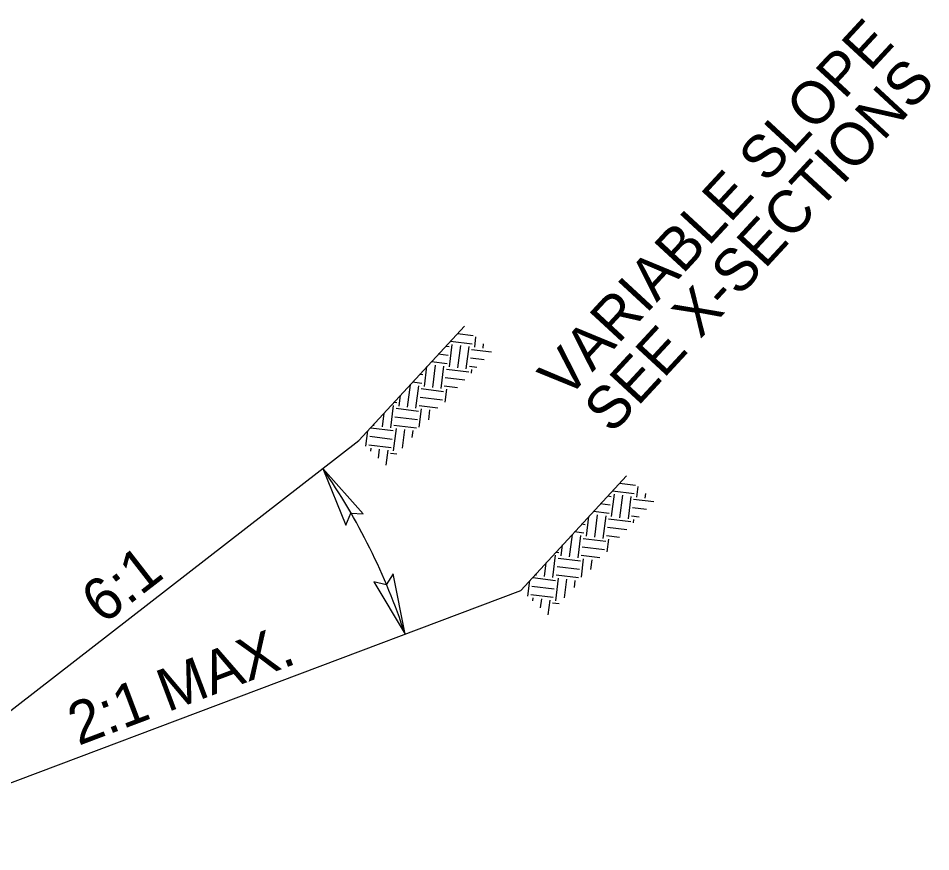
# Model space of a CAD drawing. Extents: x 1768274 to 1769121, y 999922 to 1000687.
# Drawn here: x 1769052.44 to 1769082.83, y 1000010.14 to 1000037.91 of the extents above; entities that cross this region are included whole.
import ezdxf

# ---------------------------------------------------------------- set-up
doc = ezdxf.new("R2010")
doc.units = 0
doc.layers.add('E_NCDOT_Terrain_Model_Triangles', color=7, linetype='Continuous')

msp = doc.modelspace()

# ---------------------------------------------------------------- linework, layer by layer
at = {"layer": 'E_NCDOT_Terrain_Model_Triangles'}
for p, q in [((1769063.78, 1000023.837), (1769067.304, 1000027.65)), ((1769063.78, 1000023.837), (1769067.304, 1000027.65)), ((1769067.56, 1000027.051), (1769066.834, 1000027.141)), ((1769067.56, 1000027.051), (1769066.834, 1000027.141)), ((1769067.595, 1000027.331), (1769067.07, 1000027.396)), ((1769067.595, 1000027.331), (1769067.07, 1000027.396)), ((1769067.642, 1000026.947), (1769067.685, 1000027.298)), ((1769067.642, 1000026.947), (1769067.685, 1000027.298)), ((1769066.791, 1000026.957), (1769066.677, 1000026.971)), ((1769066.791, 1000026.957), (1769066.677, 1000026.971)), ((1769066.803, 1000026.293), (1769066.896, 1000027.039)), ((1769066.803, 1000026.293), (1769066.896, 1000027.039)), ((1769067.083, 1000026.258), (1769067.175, 1000027.004)), ((1769067.083, 1000026.258), (1769067.175, 1000027.004)), ((1769067.363, 1000026.224), (1769067.455, 1000026.97)), ((1769067.363, 1000026.224), (1769067.455, 1000026.97)), ((1769068.205, 1000026.782), (1769067.537, 1000026.865)), ((1769068.205, 1000026.782), (1769067.537, 1000026.865)), ((1769067.922, 1000026.912), (1769067.94, 1000027.062)), ((1769067.922, 1000026.912), (1769067.94, 1000027.062)), ((1769066.756, 1000026.677), (1769066.428, 1000026.718)), ((1769066.756, 1000026.677), (1769066.428, 1000026.718)), ((1769067.961, 1000026.528), (1769067.502, 1000026.585)), ((1769067.961, 1000026.528), (1769067.502, 1000026.585)), ((1769065.965, 1000025.639), (1769066.047, 1000026.303)), ((1769065.965, 1000025.639), (1769066.047, 1000026.303)), ((1769066.722, 1000026.398), (1769066.206, 1000026.461)), ((1769066.722, 1000026.398), (1769066.206, 1000026.461)), ((1769066.245, 1000025.604), (1769066.337, 1000026.35)), ((1769066.245, 1000025.604), (1769066.337, 1000026.35)), ((1769066.525, 1000025.57), (1769066.617, 1000026.316)), ((1769066.525, 1000025.57), (1769066.617, 1000026.316)), ((1769067.716, 1000026.275), (1769067.468, 1000026.305)), ((1769067.716, 1000026.275), (1769067.468, 1000026.305)), ((1769065.918, 1000026.023), (1769065.803, 1000026.038)), ((1769065.918, 1000026.023), (1769065.803, 1000026.038)), ((1769067.309, 1000025.851), (1769066.664, 1000025.931)), ((1769067.309, 1000025.851), (1769066.664, 1000025.931)), ((1769067.445, 1000026.119), (1769066.699, 1000026.211)), ((1769067.445, 1000026.119), (1769066.699, 1000026.211)), ((1769067.535, 1000026.087), (1769067.55, 1000026.201)), ((1769067.535, 1000026.087), (1769067.55, 1000026.201)), ((1769065.406, 1000024.95), (1769065.499, 1000025.697)), ((1769065.406, 1000024.95), (1769065.499, 1000025.697)), ((1769065.883, 1000025.744), (1769065.569, 1000025.783)), ((1769065.883, 1000025.744), (1769065.569, 1000025.783)), ((1769065.686, 1000024.916), (1769065.778, 1000025.662)), ((1769065.686, 1000024.916), (1769065.778, 1000025.662)), ((1769067.065, 1000025.598), (1769066.629, 1000025.651)), ((1769067.065, 1000025.598), (1769066.629, 1000025.651)), ((1769065.127, 1000024.985), (1769065.172, 1000025.351)), ((1769065.127, 1000024.985), (1769065.172, 1000025.351)), ((1769066.606, 1000025.465), (1769065.86, 1000025.557)), ((1769066.606, 1000025.465), (1769065.86, 1000025.557)), ((1769066.658, 1000025.121), (1769066.711, 1000025.547)), ((1769066.658, 1000025.121), (1769066.711, 1000025.547)), ((1769064.848, 1000024.262), (1769064.94, 1000025.008)), ((1769064.848, 1000024.262), (1769064.94, 1000025.008)), ((1769065.045, 1000025.09), (1769064.944, 1000025.102)), ((1769065.045, 1000025.09), (1769064.944, 1000025.102)), ((1769066.572, 1000025.185), (1769065.826, 1000025.277)), ((1769066.572, 1000025.185), (1769065.826, 1000025.277)), ((1769064.568, 1000024.296), (1769064.625, 1000024.756)), ((1769064.568, 1000024.296), (1769064.625, 1000024.756)), ((1769065.768, 1000024.811), (1769065.022, 1000024.903)), ((1769065.768, 1000024.811), (1769065.022, 1000024.903)), ((1769066.414, 1000024.921), (1769065.791, 1000024.998)), ((1769066.414, 1000024.921), (1769065.791, 1000024.998)), ((1769065.797, 1000024.28), (1769065.873, 1000024.893)), ((1769065.797, 1000024.28), (1769065.873, 1000024.893)), ((1769066.112, 1000024.529), (1769066.153, 1000024.858)), ((1769066.112, 1000024.529), (1769066.153, 1000024.858)), ((1769064.288, 1000024.331), (1769064.297, 1000024.398)), ((1769064.288, 1000024.331), (1769064.297, 1000024.398)), ((1769065.733, 1000024.531), (1769064.987, 1000024.623)), ((1769065.733, 1000024.531), (1769064.987, 1000024.623)), ((1769064.014, 1000023.647), (1769064.078, 1000024.16)), ((1769064.014, 1000023.647), (1769064.078, 1000024.16)), ((1769064.93, 1000024.157), (1769064.183, 1000024.249)), ((1769064.93, 1000024.157), (1769064.183, 1000024.249)), ((1769064.942, 1000023.493), (1769065.034, 1000024.239)), ((1769064.942, 1000023.493), (1769065.034, 1000024.239)), ((1769065.699, 1000024.251), (1769064.953, 1000024.344)), ((1769065.699, 1000024.251), (1769064.953, 1000024.344)), ((1769065.237, 1000023.583), (1769065.314, 1000024.204)), ((1769065.237, 1000023.583), (1769065.314, 1000024.204)), ((1769065.565, 1000023.938), (1769065.594, 1000024.17)), ((1769065.565, 1000023.938), (1769065.594, 1000024.17)), ((1769046.112, 1000010.138), (1769063.78, 1000023.837)), ((1769064.895, 1000023.877), (1769064.149, 1000023.97)), ((1769064.895, 1000023.877), (1769064.149, 1000023.97)), ((1769064.86, 1000023.597), (1769064.114, 1000023.69)), ((1769064.86, 1000023.597), (1769064.114, 1000023.69)), ((1769064.184, 1000023.49), (1769064.196, 1000023.585)), ((1769064.184, 1000023.49), (1769064.196, 1000023.585)), ((1769064.439, 1000023.254), (1769064.476, 1000023.55)), ((1769064.439, 1000023.254), (1769064.476, 1000023.55)), ((1769064.694, 1000023.019), (1769064.756, 1000023.516)), ((1769064.694, 1000023.019), (1769064.756, 1000023.516)), ((1769065.053, 1000023.384), (1769064.837, 1000023.411)), ((1769065.053, 1000023.384), (1769064.837, 1000023.411)), ((1769069.178, 1000018.847), (1769072.702, 1000022.66)), ((1769069.178, 1000018.847), (1769072.702, 1000022.66)), ((1769072.993, 1000022.342), (1769072.468, 1000022.407)), ((1769072.993, 1000022.342), (1769072.468, 1000022.407)), ((1769073.04, 1000021.957), (1769073.083, 1000022.308)), ((1769073.04, 1000021.957), (1769073.083, 1000022.308)), ((1769072.189, 1000021.968), (1769072.075, 1000021.982)), ((1769072.189, 1000021.968), (1769072.075, 1000021.982)), ((1769072.201, 1000021.303), (1769072.294, 1000022.049)), ((1769072.201, 1000021.303), (1769072.294, 1000022.049)), ((1769072.958, 1000022.062), (1769072.232, 1000022.152)), ((1769072.958, 1000022.062), (1769072.232, 1000022.152)), ((1769072.481, 1000021.269), (1769072.573, 1000022.015)), ((1769072.481, 1000021.269), (1769072.573, 1000022.015)), ((1769072.761, 1000021.234), (1769072.853, 1000021.98)), ((1769072.761, 1000021.234), (1769072.853, 1000021.98)), ((1769073.32, 1000021.922), (1769073.338, 1000022.072)), ((1769073.32, 1000021.922), (1769073.338, 1000022.072)), ((1769072.154, 1000021.688), (1769071.826, 1000021.728)), ((1769072.154, 1000021.688), (1769071.826, 1000021.728)), ((1769073.603, 1000021.793), (1769072.935, 1000021.875)), ((1769073.603, 1000021.793), (1769072.935, 1000021.875)), ((1769072.12, 1000021.408), (1769071.604, 1000021.472)), ((1769072.12, 1000021.408), (1769071.604, 1000021.472)), ((1769071.643, 1000020.615), (1769071.735, 1000021.361)), ((1769071.643, 1000020.615), (1769071.735, 1000021.361)), ((1769073.359, 1000021.539), (1769072.9, 1000021.596)), ((1769073.359, 1000021.539), (1769072.9, 1000021.596)), ((1769071.316, 1000021.034), (1769071.201, 1000021.048)), ((1769071.316, 1000021.034), (1769071.201, 1000021.048)), ((1769071.363, 1000020.649), (1769071.445, 1000021.313)), ((1769071.363, 1000020.649), (1769071.445, 1000021.313)), ((1769071.923, 1000020.58), (1769072.015, 1000021.326)), ((1769071.923, 1000020.58), (1769072.015, 1000021.326)), ((1769072.843, 1000021.129), (1769072.097, 1000021.221)), ((1769072.843, 1000021.129), (1769072.097, 1000021.221)), ((1769073.114, 1000021.285), (1769072.866, 1000021.316)), ((1769073.114, 1000021.285), (1769072.866, 1000021.316)), ((1769072.933, 1000021.097), (1769072.947, 1000021.211)), ((1769072.933, 1000021.097), (1769072.947, 1000021.211)), ((1769071.281, 1000020.754), (1769070.967, 1000020.793)), ((1769071.281, 1000020.754), (1769070.967, 1000020.793)), ((1769072.707, 1000020.862), (1769072.062, 1000020.942)), ((1769072.707, 1000020.862), (1769072.062, 1000020.942)), ((1769070.804, 1000019.961), (1769070.897, 1000020.707)), ((1769070.804, 1000019.961), (1769070.897, 1000020.707)), ((1769071.084, 1000019.926), (1769071.176, 1000020.672)), ((1769071.084, 1000019.926), (1769071.176, 1000020.672)), ((1769072.004, 1000020.475), (1769071.258, 1000020.568)), ((1769072.004, 1000020.475), (1769071.258, 1000020.568)), ((1769072.463, 1000020.608), (1769072.027, 1000020.662)), ((1769072.463, 1000020.608), (1769072.027, 1000020.662)), ((1769072.056, 1000020.131), (1769072.109, 1000020.557)), ((1769072.056, 1000020.131), (1769072.109, 1000020.557)), ((1769070.525, 1000019.995), (1769070.57, 1000020.361)), ((1769070.525, 1000019.995), (1769070.57, 1000020.361)), ((1769071.97, 1000020.195), (1769071.224, 1000020.288)), ((1769071.97, 1000020.195), (1769071.224, 1000020.288)), ((1769070.246, 1000019.272), (1769070.338, 1000020.018)), ((1769070.246, 1000019.272), (1769070.338, 1000020.018)), ((1769070.443, 1000020.1), (1769070.341, 1000020.113)), ((1769070.443, 1000020.1), (1769070.341, 1000020.113)), ((1769071.166, 1000019.821), (1769070.42, 1000019.914)), ((1769071.166, 1000019.821), (1769070.42, 1000019.914)), ((1769071.811, 1000019.931), (1769071.189, 1000020.008)), ((1769071.811, 1000019.931), (1769071.189, 1000020.008)), ((1769071.195, 1000019.29), (1769071.271, 1000019.903)), ((1769071.195, 1000019.29), (1769071.271, 1000019.903)), ((1769071.51, 1000019.54), (1769071.551, 1000019.869)), ((1769071.51, 1000019.54), (1769071.551, 1000019.869)), ((1769069.966, 1000019.307), (1769070.023, 1000019.766)), ((1769069.966, 1000019.307), (1769070.023, 1000019.766)), ((1769071.131, 1000019.542), (1769070.385, 1000019.634)), ((1769071.131, 1000019.542), (1769070.385, 1000019.634)), ((1769070.328, 1000019.167), (1769069.581, 1000019.26)), ((1769070.328, 1000019.167), (1769069.581, 1000019.26)), ((1769069.686, 1000019.341), (1769069.695, 1000019.409)), ((1769069.686, 1000019.341), (1769069.695, 1000019.409)), ((1769070.34, 1000018.503), (1769070.432, 1000019.249)), ((1769070.34, 1000018.503), (1769070.432, 1000019.249)), ((1769071.097, 1000019.262), (1769070.351, 1000019.354)), ((1769071.097, 1000019.262), (1769070.351, 1000019.354)), ((1769069.412, 1000018.657), (1769069.476, 1000019.171)), ((1769069.412, 1000018.657), (1769069.476, 1000019.171)), ((1769070.293, 1000018.888), (1769069.547, 1000018.98)), ((1769070.293, 1000018.888), (1769069.547, 1000018.98)), ((1769070.635, 1000018.594), (1769070.712, 1000019.215)), ((1769070.635, 1000018.594), (1769070.712, 1000019.215)), ((1769070.963, 1000018.948), (1769070.992, 1000019.18)), ((1769070.963, 1000018.948), (1769070.992, 1000019.18)), ((1769046.112, 1000010.138), (1769069.178, 1000018.847)), ((1769070.258, 1000018.608), (1769069.512, 1000018.7)), ((1769070.258, 1000018.608), (1769069.512, 1000018.7)), ((1769069.582, 1000018.5), (1769069.594, 1000018.595)), ((1769069.582, 1000018.5), (1769069.594, 1000018.595)), ((1769069.837, 1000018.265), (1769069.874, 1000018.561)), ((1769069.837, 1000018.265), (1769069.874, 1000018.561)), ((1769070.092, 1000018.029), (1769070.154, 1000018.526)), ((1769070.092, 1000018.029), (1769070.154, 1000018.526)), ((1769070.451, 1000018.395), (1769070.235, 1000018.421)), ((1769070.451, 1000018.395), (1769070.235, 1000018.421))]:
    msp.add_line(p, q, dxfattribs=at)
for points in [[(1769063.933, 1000021.397), (1769062.582, 1000022.908), (1769063.347, 1000021.016), (1769063.512, 1000021.421)], [(1769064.282, 1000019.132), (1769065.321, 1000017.391), (1769064.93, 1000019.393), (1769064.69, 1000019.027)]]:
    msp.add_lwpolyline(points, close=True, dxfattribs=at)
msp.add_arc((1769045.06, 1000010.771), 21.315, 18.0931, 34.7085, dxfattribs=at)

# ---------------------------------------------------------------- texts
for s, height, rotation, p in [('VARIABLE SLOPE', 1.42097, 47.2512, (1769070.695, 1000025.167)), ('SEE X-SECTIONS', 1.42097, 47.2512, (1769072.211, 1000024.023)), ('6:1', 1.421, 37.7887, (1769055.265, 1000017.684)), ('2:1 MAX.', 1.421, 20.686, (1769054.444, 1000013.663))]:
    msp.add_text(s, height=height, rotation=rotation, dxfattribs=at).set_placement(p)

doc.saveas('drawing.dxf')
